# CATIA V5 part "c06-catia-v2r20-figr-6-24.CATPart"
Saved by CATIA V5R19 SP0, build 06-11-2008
Part number: Part1
Bounding box of the stored display mesh (mm): x -75 to 75, y -50 to 50, z -50 to 50
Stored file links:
  D:\Shriniwas\v5_r19\Part files\cat_p\c06\Figure 6-24.CATPart
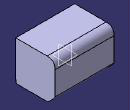
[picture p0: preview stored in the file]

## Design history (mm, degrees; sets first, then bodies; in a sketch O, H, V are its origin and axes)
Body1 (main body)
  Sketch1 on yz-plane, origin (0, 0, 0), H (0, 1, 0), V (0, 0, 1)
    line L1 (-50, 50) -> (50, 50)
    line L2 (50, 50) -> (50, -50)
    line L3 (50, -50) -> (-50, -50)
    line L4 (-50, -50) -> (-50, 50)
    length L2 = 100
    length L1 = 100
    distance L1 H = 50
    distance L4 V = 50
    horizontal: L1 H, L3 H
    vertical: L2 V, L4 V
  Pad1: profile Sketch1, direction (-1, 0, 0), length 75, mirrored extent
  Fillet1: radius 20, conic ratio 0.5, on edge [face of Pad1 from Sketch1.L2 | face of Pad1 from Sketch1.L1]
  Fillet2: radius 20, conic ratio 0.9, on edge [face of Pad1 from Sketch1.L4 | face of Pad1 from Sketch1.L3]
  Fillet3: radius 20, conic ratio 0.1, on edge [face of Pad1 from Sketch1.L3 | face of Pad1 from Sketch1.L2]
